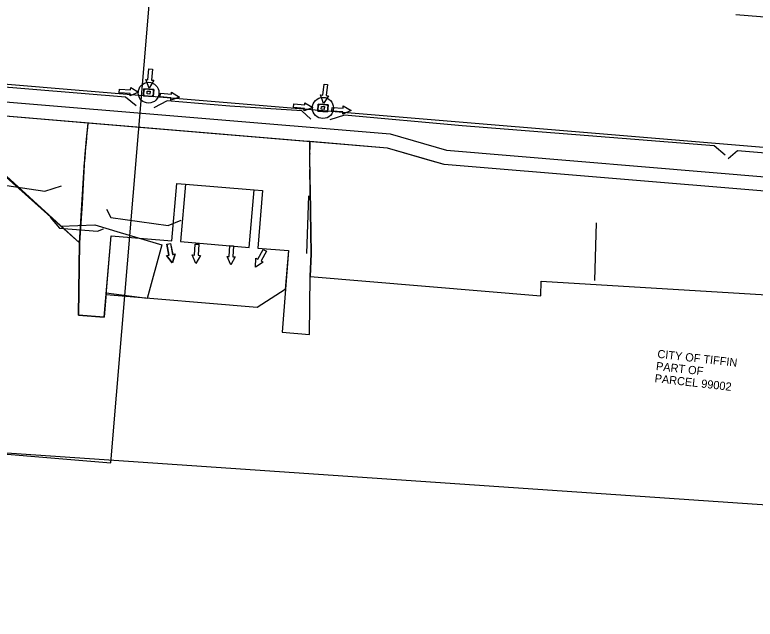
# Model space of a CAD drawing. Extents: x 20499990 to 20505779, y 7953198 to 7954399.
# Drawn here: x 20504117.2 to 20504373.6, y 7953486.1 to 7953695.2 of the extents above; entities that cross this region are included whole.
import ezdxf

# ---------------------------------------------------------------- set-up
doc = ezdxf.new("R2010")
doc.units = 0
for name, color, linetype in [('Building', 7, 'Continuous'), ('ClearGrub', 7, 'Continuous'), ('dsnCellElements', 7, 'Continuous'), ('ErosionControl', 7, 'Continuous'), ('NamedBoundary', 7, 'Continuous'), ('Seeding', 7, 'Continuous'), ('Text', 7, 'Continuous')]:
    doc.layers.add(name, color=color, linetype=linetype)

msp = doc.modelspace()

# ---------------------------------------------------------------- linework, layer by layer
at = {"layer": 'Building'}
for p, q in [((20504431.47, 7953689.85), (20504366.9, 7953695.23)), ((20503815.08, 7953690.11), (20504247.14, 7953654.05)), ((20504142.52, 7953657.76), (20503912.79, 7953676.94)), ((20504142.52, 7953657.76), (20504142.52, 7953657.76)), ((20504142.52, 7953657.76), (20504142.52, 7953657.76)), ((20504142.52, 7953657.76), (20504142.52, 7953657.76)), ((20504247.14, 7953654.05), (20504266.74, 7953648.4)), ((20504219.39, 7953651.35), (20504219.26, 7953645.59)), ((20504246.23, 7953649.11), (20504219.39, 7953651.35)), ((20504260.92, 7953644.87), (20504246.23, 7953649.11)), ((20504266.74, 7953648.4), (20504496.4, 7953629.24)), ((20504219.26, 7953645.59), (20504219.29, 7953643.07)), ((20504265.83, 7953643.46), (20504260.92, 7953644.87)), ((20504141.32, 7953644.33), (20504141.32, 7953644.33)), ((20504219.29, 7953643.09), (20504219.38, 7953641.68)), ((20504496.05, 7953624.25), (20504265.83, 7953643.46))]:
    msp.add_line(p, q, dxfattribs=at)
for points in [[(20504427.73, 7953645), (20504246.09, 7953660.16), (20503289.64, 7953739.98)], [(20503935.36, 7953658.74), (20503935.36, 7953658.74), (20504108.89, 7953644.26), (20504139.58, 7953616.36), (20504141.32, 7953644.33)], [(20504141.32, 7953644.33), (20504141.32, 7953644.33), (20504141.32, 7953644.33)], [(20504141.32, 7953644.33), (20504141.32, 7953644.33)], [(20504219.38, 7953641.68), (20504219.41, 7953638.19)], [(20504219.41, 7953638.19), (20504219.43, 7953634.7)], [(20504219.43, 7953634.7), (20504219.82, 7953612.46)], [(20504219.82, 7953612.46), (20504219.46, 7953604.68)], [(20504219.46, 7953604.68), (20504299.4, 7953598.01), (20504299.45, 7953603.02), (20504541.05, 7953588.36)]]:
    msp.add_lwpolyline(points, dxfattribs=at)
msp.add_arc((20504716.34, 7953599.84), 576.74, 174.23541, 175.57497, dxfattribs=at)
at = {"layer": 'ClearGrub'}
msp.add_lwpolyline([(20504153.66, 7953619.94), (20504168.18, 7953615.65), (20504163.01, 7953597.09), (20504148.89, 7953598.86), (20504148.89, 7953598.86), (20504148.2, 7953590.56), (20504139.32, 7953591.3), (20504139.58, 7953616.36), (20504133.11, 7953622.14), (20504144.94, 7953622.52)], close=True, dxfattribs=at)
at = {"layer": 'dsnCellElements'}
for p, q in [((20504163.33, 7953672.75), (20504163.62, 7953676.56)), ((20504163.62, 7953676.56), (20504164.89, 7953676.46)), ((20504164.89, 7953676.46), (20504164.6, 7953672.66)), ((20504163.75, 7953669.85), (20504162.54, 7953672.81)), ((20504162.54, 7953672.81), (20504163.33, 7953672.75)), ((20504165.39, 7953672.6), (20504163.75, 7953669.85)), ((20504164.6, 7953672.66), (20504165.39, 7953672.6)), ((20504223.82, 7953667.43), (20504224.28, 7953671.22)), ((20504224.28, 7953671.22), (20504225.54, 7953671.07)), ((20504225.54, 7953671.07), (20504225.08, 7953667.28)), ((20504153.4, 7953668.28), (20504153.49, 7953669.55)), ((20504157.21, 7953668.03), (20504153.4, 7953668.28)), ((20504153.49, 7953669.55), (20504157.29, 7953669.3)), ((20504160.11, 7953668.48), (20504157.16, 7953667.24)), ((20504157.16, 7953667.24), (20504157.21, 7953668.03)), ((20504157.29, 7953669.3), (20504157.35, 7953670.09)), ((20504157.35, 7953670.09), (20504160.11, 7953668.48)), ((20504167.5, 7953666.86), (20504167.63, 7953668.13)), ((20504167.63, 7953668.13), (20504171.43, 7953667.73)), ((20504171.43, 7953667.73), (20504171.51, 7953668.52)), ((20504171.51, 7953668.52), (20504174.21, 7953666.79)), ((20504171.29, 7953666.46), (20504167.5, 7953666.86)), ((20504174.21, 7953666.79), (20504171.21, 7953665.67)), ((20504171.21, 7953665.67), (20504171.29, 7953666.46)), ((20504224.11, 7953664.51), (20504223.03, 7953667.52)), ((20504223.03, 7953667.52), (20504223.82, 7953667.43)), ((20504225.87, 7953667.18), (20504224.11, 7953664.51)), ((20504225.08, 7953667.28), (20504225.87, 7953667.18)), ((20504213.69, 7953663.13), (20504213.82, 7953664.4)), ((20504217.49, 7953662.76), (20504213.69, 7953663.13)), ((20504213.82, 7953664.4), (20504217.62, 7953664.03)), ((20504220.4, 7953663.12), (20504217.42, 7953661.97)), ((20504217.42, 7953661.97), (20504217.49, 7953662.76)), ((20504217.62, 7953664.03), (20504217.69, 7953664.82)), ((20504217.69, 7953664.82), (20504220.4, 7953663.12)), ((20504226.98, 7953661.86), (20504227.05, 7953663.13)), ((20504227.05, 7953663.13), (20504230.86, 7953662.9)), ((20504230.86, 7953662.9), (20504230.91, 7953663.7)), ((20504230.91, 7953663.7), (20504233.68, 7953662.1)), ((20504230.78, 7953661.63), (20504226.98, 7953661.86)), ((20504233.68, 7953662.1), (20504230.74, 7953660.84)), ((20504230.74, 7953660.84), (20504230.78, 7953661.63)), ((20504169.92, 7953615.86), (20504171.17, 7953616.08)), ((20504170.57, 7953612.1), (20504169.92, 7953615.86)), ((20504169.93, 7953615.81), (20504171.18, 7953616.06)), ((20504170.68, 7953612.07), (20504169.93, 7953615.81)), ((20504171.17, 7953616.08), (20504171.82, 7953612.32)), ((20504171.18, 7953616.06), (20504171.93, 7953612.32)), ((20504179.45, 7953612.08), (20504179.65, 7953615.89)), ((20504179.65, 7953615.89), (20504180.92, 7953615.82)), ((20504180.92, 7953615.82), (20504180.72, 7953612.01)), ((20504191.5, 7953611.54), (20504191.69, 7953615.35)), ((20504191.69, 7953615.35), (20504192.96, 7953615.29)), ((20504192.96, 7953615.29), (20504192.77, 7953611.48)), ((20504201.39, 7953610.66), (20504203.24, 7953614)), ((20504203.24, 7953614), (20504204.35, 7953613.39)), ((20504169.78, 7953611.97), (20504170.57, 7953612.1)), ((20504171.68, 7953609.39), (20504169.78, 7953611.97)), ((20504169.9, 7953611.91), (20504170.68, 7953612.07)), ((20504171.87, 7953609.39), (20504169.9, 7953611.91)), ((20504172.6, 7953612.45), (20504171.68, 7953609.39)), ((20504171.82, 7953612.32), (20504172.6, 7953612.45)), ((20504172.71, 7953612.48), (20504171.87, 7953609.39)), ((20504171.93, 7953612.32), (20504172.71, 7953612.48)), ((20504179.94, 7953609.18), (20504178.66, 7953612.12)), ((20504178.66, 7953612.12), (20504179.45, 7953612.08)), ((20504181.52, 7953611.97), (20504179.94, 7953609.18)), ((20504180.72, 7953612.01), (20504181.52, 7953611.97)), ((20504191.99, 7953608.65), (20504190.71, 7953611.58)), ((20504190.71, 7953611.58), (20504191.5, 7953611.54)), ((20504193.56, 7953611.44), (20504191.99, 7953608.65)), ((20504192.77, 7953611.48), (20504193.56, 7953611.44)), ((20504204.35, 7953613.39), (20504202.51, 7953610.05)), ((20504200.57, 7953607.85), (20504200.7, 7953611.05)), ((20504203.2, 7953609.66), (20504200.57, 7953607.85)), ((20504200.7, 7953611.05), (20504201.39, 7953610.66)), ((20504202.51, 7953610.05), (20504203.2, 7953609.66))]:
    msp.add_line(p, q, dxfattribs=at)
at = {"layer": 'ErosionControl'}
for p, q in [((20504161.91, 7953669.31), (20504162.08, 7953669.3)), ((20504162.08, 7953669.3), (20504162.26, 7953669.45)), ((20504162.27, 7953669.62), (20504162.26, 7953669.45)), ((20504164.81, 7953666.98), (20504164.83, 7953667.15)), ((20504165.01, 7953667.3), (20504164.83, 7953667.15)), ((20504165.18, 7953667.29), (20504165.01, 7953667.3)), ((20504222.26, 7953664.01), (20504222.43, 7953663.99)), ((20504222.43, 7953663.99), (20504222.61, 7953664.15)), ((20504222.63, 7953664.31), (20504222.61, 7953664.15)), ((20504225.17, 7953661.67), (20504225.18, 7953661.84)), ((20504225.36, 7953662), (20504225.18, 7953661.84)), ((20504225.53, 7953661.98), (20504225.36, 7953662)), ((20504142.52, 7953657.76), (20504141.98, 7953652.16)), ((20504218.32, 7953651.44), (20504142.52, 7953657.76)), ((20504142.52, 7953657.76), (20504142.52, 7953657.76)), ((20504141.98, 7953652.16), (20504141.39, 7953645.59)), ((20504219.39, 7953651.35), (20504218.32, 7953651.44)), ((20504219.33, 7953647.26), (20504219.39, 7953651.35)), ((20504219.39, 7953651.35), (20504219.39, 7953651.35)), ((20504141.4, 7953645.61), (20504141.39, 7953645.59)), ((20504219.43, 7953634.7), (20504219.38, 7953641.68)), ((20504176.3, 7953636.66), (20504200.06, 7953634.68)), ((20504218.9, 7953632.58), (20504218.25, 7953612.59)), ((20504318.53, 7953623.26), (20504317.88, 7953603.27))]:
    msp.add_line(p, q, dxfattribs=at)
for points in [[(20504159.22, 7953663.7), (20504155.57, 7953666.68), (20504091.33, 7953672.01), (20504032.85, 7953676.87), (20504027.91, 7953677.4), (20504024.82, 7953675.01)], [(20504219.77, 7953659.13), (20504216.59, 7953662.04), (20504191.63, 7953663.63), (20504170, 7953665.46), (20504165.31, 7953663.09)], [(20504363.11, 7953646.69), (20504359.32, 7953649.86), (20504327.47, 7953652.42), (20504272.08, 7953656.83), (20504231.41, 7953660.54), (20504226.3, 7953658.86)], [(20504364.18, 7953645.5), (20504367.41, 7953648.26), (20504481.84, 7953638.74), (20504487.64, 7953635.79)], [(20504141.39, 7953645.59), (20504141.39, 7953645.59), (20504140.51, 7953629.88), (20504139.58, 7953616.36), (20504139.32, 7953591.3), (20504148.2, 7953590.56)], [(20504141.39, 7953645.59), (20504141.39, 7953645.59)], [(20504141.39, 7953645.59), (20504141.39, 7953645.59)], [(20504108.45, 7953639.59), (20504111.27, 7953636.67), (20504127.63, 7953634.23), (20504133.38, 7953636.08)], [(20504148.2, 7953590.56), (20504150.55, 7953618.74), (20504171.65, 7953616.98), (20504173.31, 7953636.91), (20504176.3, 7953636.66), (20504200.06, 7953634.68), (20504203.04, 7953634.43), (20504201.39, 7953614.5), (20504212, 7953613.62), (20504209.76, 7953585.42)], [(20504200.06, 7953634.68), (20504203.04, 7953634.43), (20504201.39, 7953614.5), (20504212, 7953613.62), (20504210.88, 7953600.18), (20504201.17, 7953593.91), (20504148.84, 7953598.28), (20504150.55, 7953618.74), (20504171.65, 7953616.98), (20504173.31, 7953636.91), (20504176.3, 7953636.66)], [(20504200.06, 7953634.68), (20504203.04, 7953634.43), (20504201.39, 7953614.5), (20504212, 7953613.62), (20504210.88, 7953600.18), (20504201.17, 7953593.91), (20504148.84, 7953598.28), (20504150.55, 7953618.74), (20504171.65, 7953616.98), (20504173.31, 7953636.91), (20504176.3, 7953636.66)], [(20504176.3, 7953636.66), (20504174.64, 7953616.73), (20504198.4, 7953614.75), (20504200.06, 7953634.68)], [(20504209.76, 7953585.42), (20504219.25, 7953584.63), (20504219.46, 7953604.68), (20504219.82, 7953612.46), (20504219.43, 7953634.7)], [(20504149, 7953628), (20504150.43, 7953625.05), (20504170.31, 7953622.29), (20504174.78, 7953624.2)], [(20504129.53, 7953625.22), (20504132.65, 7953621.42), (20504145.85, 7953620.35), (20504147.89, 7953621.13)]]:
    msp.add_lwpolyline(points, dxfattribs=at)
for points in [[(20504161.74, 7953667.23), (20504165.15, 7953666.96), (20504165.34, 7953669.38), (20504161.94, 7953669.65)], [(20504161.94, 7953669.65), (20504165.34, 7953669.38), (20504165.15, 7953666.96), (20504161.74, 7953667.23)], [(20504162.08, 7953669.3), (20504161.91, 7953669.31), (20504161.94, 7953669.65), (20504162.11, 7953669.64)], [(20504163.08, 7953668.85), (20504164.09, 7953668.77), (20504164.01, 7953667.76), (20504163, 7953667.84)], [(20504165.32, 7953669.04), (20504165.15, 7953669.05), (20504165.18, 7953669.39), (20504165.34, 7953669.38)], [(20504161.91, 7953667.22), (20504161.74, 7953667.23), (20504161.77, 7953667.57), (20504161.94, 7953667.55)], [(20504165.15, 7953666.96), (20504164.98, 7953666.97), (20504165.01, 7953667.3), (20504165.18, 7953667.29)], [(20504222.1, 7953661.92), (20504225.5, 7953661.65), (20504225.7, 7953664.07), (20504222.29, 7953664.34)], [(20504222.29, 7953664.34), (20504225.7, 7953664.07), (20504225.5, 7953661.65), (20504222.1, 7953661.92)], [(20504222.43, 7953663.99), (20504222.26, 7953664.01), (20504222.29, 7953664.34), (20504222.46, 7953664.33)], [(20504223.43, 7953663.54), (20504224.44, 7953663.46), (20504224.36, 7953662.45), (20504223.35, 7953662.53)], [(20504225.67, 7953663.73), (20504225.5, 7953663.75), (20504225.53, 7953664.08), (20504225.7, 7953664.07)], [(20504222.26, 7953661.91), (20504222.1, 7953661.92), (20504222.12, 7953662.26), (20504222.29, 7953662.24)], [(20504225.5, 7953661.65), (20504225.33, 7953661.66), (20504225.36, 7953662), (20504225.53, 7953661.98)]]:
    msp.add_lwpolyline(points, close=True, dxfattribs=at)
for centre, radius in [((20504163.55, 7953668.27), 3.6), ((20504223.9, 7953663.01), 3.66)]:
    msp.add_circle(centre, radius, dxfattribs=at)
msp.add_arc((20504258.61, 7953644.84), 39.36, 176.4737, 184.5967, dxfattribs=at)
at = {"layer": 'NamedBoundary'}
for points in [[(20503238.22, 7953917.37), (20503213.27, 7953618.41), (20504150.52, 7953540.19), (20504175.47, 7953839.15)], [(20504038.63, 7953849.54), (20504018.15, 7953550.24), (20504956.36, 7953486.07), (20504976.83, 7953785.37)]]:
    msp.add_lwpolyline(points, close=True, dxfattribs=at)
at = {"layer": 'Seeding'}
for p, q in [((20504431.47, 7953689.85), (20504366.9, 7953695.23)), ((20503815.08, 7953690.11), (20504247.14, 7953654.05)), ((20504246.23, 7953649.11), (20503815.16, 7953685.08)), ((20504247.14, 7953654.05), (20504266.74, 7953648.4)), ((20504265.83, 7953643.46), (20504246.23, 7953649.11)), ((20504266.74, 7953648.4), (20504496.4, 7953629.24)), ((20504496.05, 7953624.25), (20504265.83, 7953643.46))]:
    msp.add_line(p, q, dxfattribs=at)
for points in [[(20504427.73, 7953645), (20504246.09, 7953660.16), (20503289.64, 7953739.98)], [(20503889.46, 7953622.18), (20503930.78, 7953618.73), (20503935.07, 7953658.52), (20504108.6, 7953644.04), (20504139.58, 7953616.36), (20504139.32, 7953591.3), (20504148.2, 7953590.56)], [(20504148.2, 7953590.56), (20504150.55, 7953618.74), (20504171.65, 7953616.98), (20504173.31, 7953636.91), (20504176.3, 7953636.66), (20504200.06, 7953634.68), (20504203.04, 7953634.43), (20504201.39, 7953614.5), (20504212, 7953613.62), (20504209.76, 7953585.42)], [(20504209.76, 7953585.42), (20504219.25, 7953584.63), (20504219.46, 7953604.68), (20504299.4, 7953598.01), (20504299.45, 7953603.02), (20504541.05, 7953588.36)]]:
    msp.add_lwpolyline(points, dxfattribs=at)

# ---------------------------------------------------------------- texts
at = {"layer": 'Text'}
for s, height, p in [('CITY OF TIFFIN', 2.8346, (20504339.58, 7953576.55)), ('PART OF ', 2.835, (20504339.1, 7953572.32)), ('PARCEL 99002', 2.8346, (20504338.62, 7953568.1))]:
    msp.add_text(s, height=height, rotation=353.4901, dxfattribs=at).set_placement(p)

doc.saveas('drawing.dxf')
